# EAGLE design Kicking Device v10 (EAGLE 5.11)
OC_FARNELL: 1685056

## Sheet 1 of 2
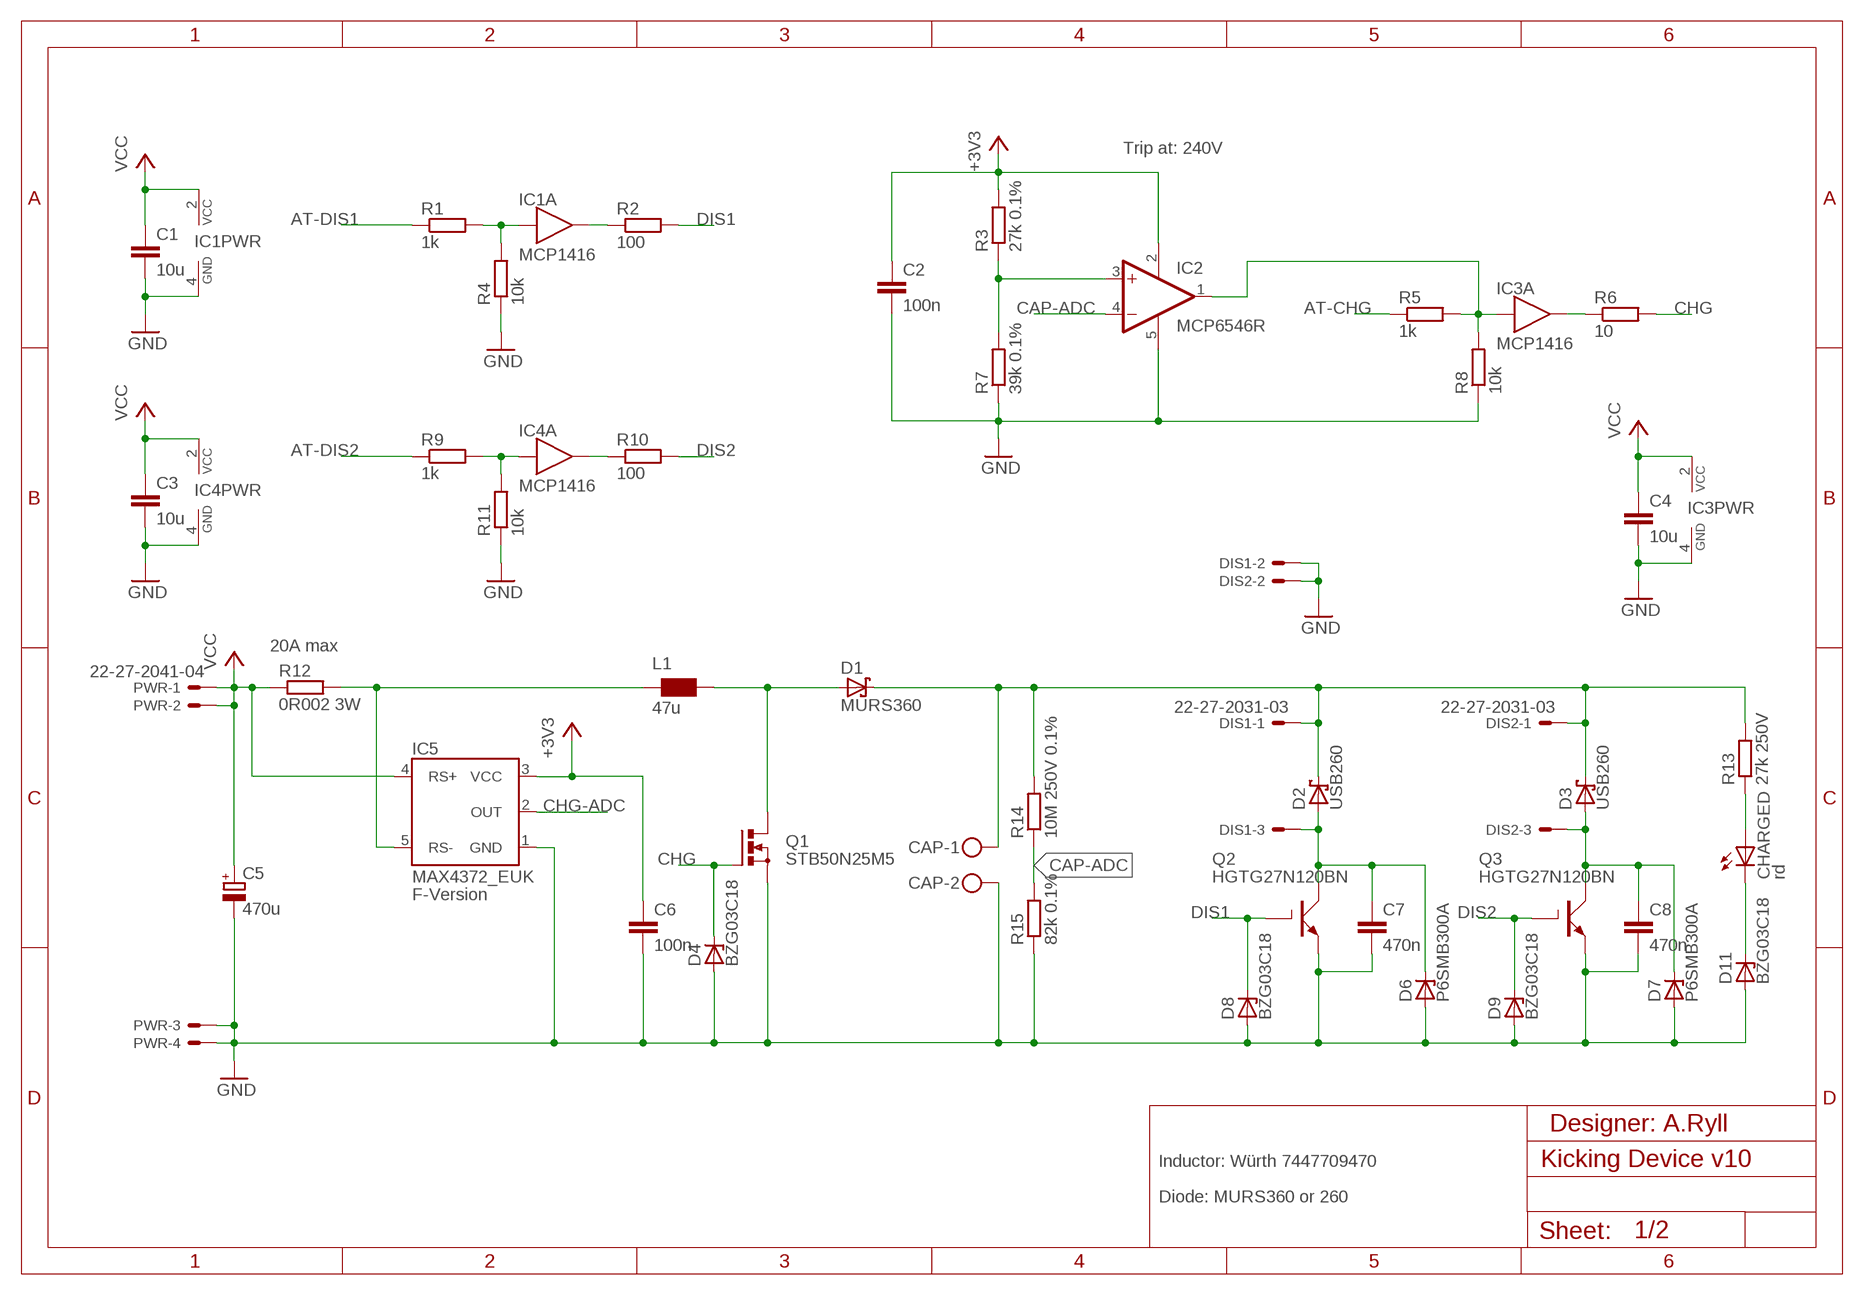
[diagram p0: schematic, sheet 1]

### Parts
C1  10u  C-EUC0805  [C0805]
C2  100n  C-EUC0805  [C0805]
C3  10u  C-EUC0805  [C0805]
C4  10u  C-EUC0805  [C0805]
C5  470u  CPOL-EUG  [PANASONIC_G]
C6  100n  C-EUC0805  [C0805]
C7  470n  C-EUC1812  [C1812]
C8  470n  C-EUC1812  [C1812]
CAP  MKDSN1,5/2-5,08  [MKDSN1,5/2-5,08]
CHARGED  rd  LEDCHIP-LED0805  [CHIP-LED0805]
D1  MURS360  SCHOTTKY-DIODESMC  [SMC]
D2  USB260  SCHOTTKY-DIODESMD  [SMB]
D3  USB260  SCHOTTKY-DIODESMD  [SMB]
D4  BZG03C18  ZENER-DIODESMB  [SMB]
D6  P6SMB300A  ZENER-DIODESMB  [SMB]
D7  P6SMB300A  ZENER-DIODESMB  [SMB]
D8  BZG03C18  ZENER-DIODESMB  [SMB]
D9  BZG03C18  ZENER-DIODESMB  [SMB]
D11  BZG03C18  ZENER-DIODESMB  [SMB]
DIS1  22-27-2031-03  [6410-03]
DIS2  22-27-2031-03  [6410-03]
IC1  MCP1416  [SOT23-5]
IC2  MCP6546R  MCP601R  [SOT23-5]
IC3  MCP1416  [SOT23-5]
IC4  MCP1416  [SOT23-5]
IC5  MAX4372_EUK  [SOT23-5]
L1  47u  WE-PD_L/XL/XXL  [WE-PD_L/XL/XXL]
PWR  22-27-2041-04  [6410-04]
Q1  STB50N25M5  NMOS-D2PAK  [D2PAK]
Q2  HGTG27N120BN  IGBT-TO247  [TO247BV]
Q3  HGTG27N120BN  IGBT-TO247  [TO247BV]
R1  1k  R-EU_R0805  [R0805]
R2  100  R-EU_R0805  [R0805]
R3  27k 0.1%  R-EU_R0805  [R0805]
R4  10k  R-EU_R0805  [R0805]
R5  1k  R-EU_R0805  [R0805]
R6  10  R-EU_R0805  [R0805]
R7  39k 0.1%  R-EU_R0805  [R0805]
R8  10k  R-EU_R0805  [R0805]
R9  1k  R-EU_R0805  [R0805]
R10  100  R-EU_R0805  [R0805]
R11  10k  R-EU_R0805  [R0805]
R12  0R002 3W  R-EU_R2512  [R2512]
R13  27k 250V  R-EU_R1206  [R1206]
R14  10M 250V 0.1%  R-EU_R1206  [R1206]
R15  82k 0.1%  R-EU_R1206  [R1206]

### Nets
400-HIGH [HV]: D1.A L1.1 Q1.2(D)
400-SW: IC5.5(RS-) L1.2 R12.2
+3V3: C2.1 C6.1 IC2.2(V+) IC5.3(VCC) R3.2 ; also sheet 2
AT-CHG: R5.1 ; also sheet 2
AT-DIS1: R1.1 ; also sheet 2
AT-DIS2: R9.1 ; also sheet 2
CAP-ADC: IC2.4(-IN) R14.1 R15.2 ; also sheet 2
CAPVCC [HV]: CAP.1 D1.C D2.C D3.C DIS1.1 DIS2.1 R13.2 R14.2
CHG: D4.C Q1.1(G) R6.2
CHG-ADC: IC5.2(OUT) ; also sheet 2
CHG-IN: IC2.1(OUT) IC3.3(A:IN) R5.2 R8.2
DIS1: D8.C Q2.1(G) R2.2
DIS1-SW [HV]: C7.1 D2.A D6.C DIS1.3 Q2.2(C)
DIS2: D9.C Q3.1(G) R10.2
DIS2-SW [HV]: C8.1 D3.A D7.C DIS2.3 Q3.2(C)
GND: C1.2 C2.2 C3.2 C4.2 C5.- C6.2 C7.2 C8.2 CAP.2 D4.A D6.A D7.A D8.A D9.A D11.A DIS1.2 DIS2.2 IC1.4(PWR:GND) IC2.5(V-) IC3.4(PWR:GND) IC4.4(PWR:GND) IC5.1(GND) PWR.3 PWR.4 Q1.3(S) Q2.3(E) Q3.3(E) R4.1 R7.1 R8.1 R11.1 R15.1 ; also sheet 2
N$2: IC1.3(A:IN) R1.2 R4.2
N$3: IC2.3(+IN) R3.1 R7.2
N$5: IC1.5(A:OUT) R2.1
N$6: CHARGED.A R13.1
N$10: CHARGED.C D11.C
N$11: IC4.3(A:IN) R9.2 R11.2
N$17: IC4.5(A:OUT) R10.1
N$19: IC3.5(A:OUT) R6.1
VCC: C1.1 C3.1 C4.1 C5.+ IC1.2(PWR:VCC) IC3.2(PWR:VCC) IC4.2(PWR:VCC) IC5.4(RS+) PWR.1 PWR.2 R12.1

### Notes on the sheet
- Trip at: 240V
- 20A max
- F-Version
- Designer: A.Ryll
- Inductor: Würth 7447709470
- Diode: MURS360 or 260

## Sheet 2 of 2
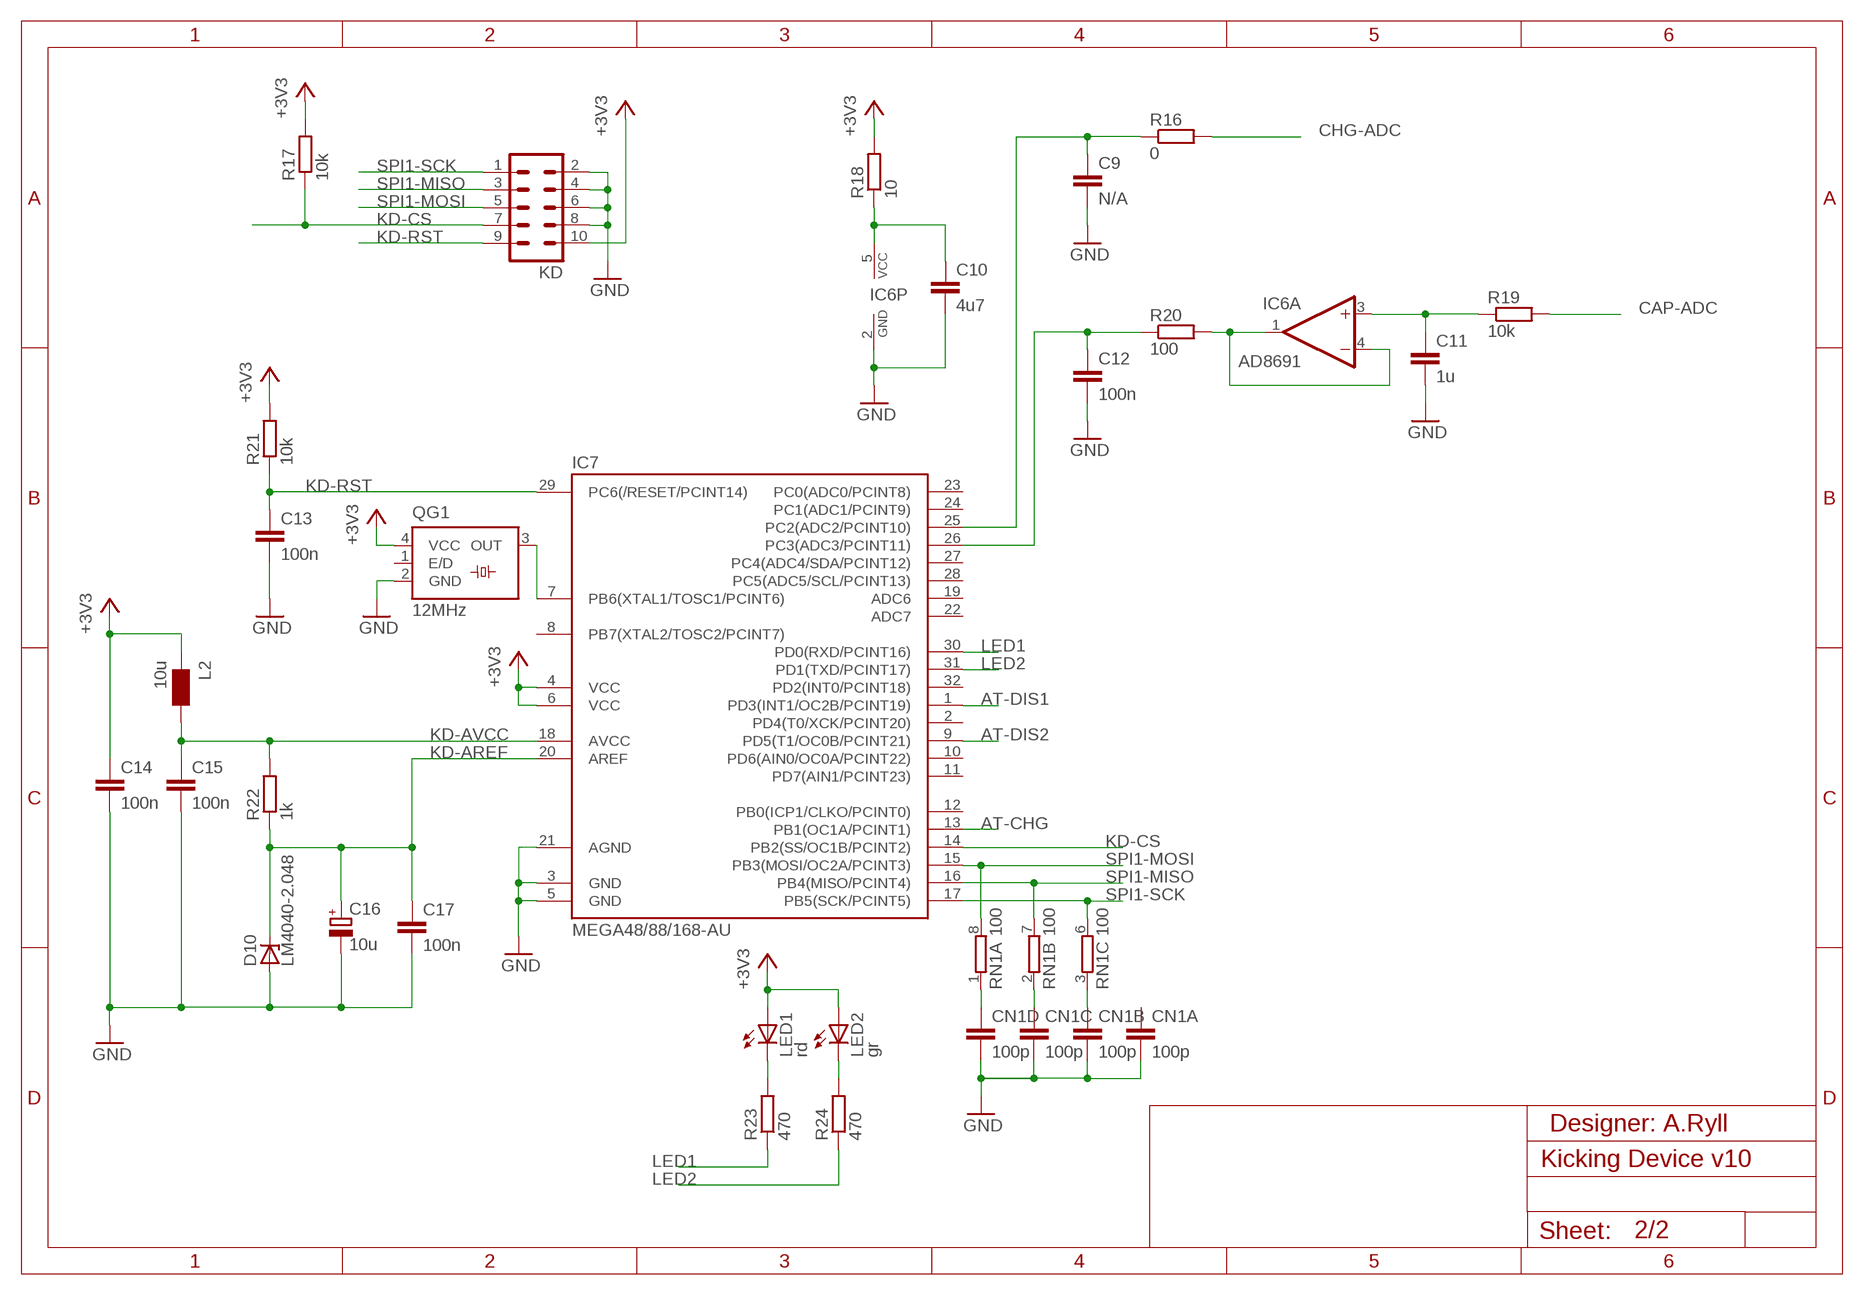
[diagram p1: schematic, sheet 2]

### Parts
C9  N/A  C-EUC0805  [C0805]
C10  4u7  C-EUC0805  [C0805]
C11  1u  C-EUC0805  [C0805]
C12  100n  C-EUC0805  [C0805]
C13  100n  C-EUC0805  [C0805]
C14  100n  C-EUC0805  [C0805]
C15  100n  C-EUC0805  [C0805]
C16  10u  CPOL-EUC/6032-28W  [C/6032-28W]
C17  100n  C-EUC0805  [C0805]
CN1  100p  4C-NCAY16  [CAY16]
D10  LM4040-2.048  ZENER-DIODELM4040  [SOT23]
IC6  AD8691  AD-OP1RT  [SOT23-5]
IC7  MEGA48/88/168-AU  [TQFP32-08]
KD  ML10  [ML10]
L2  10u  WE-MI_0805  [0805]
LED1  rd  LEDCHIP-LED0805  [CHIP-LED0805]
LED2  gr  LEDCHIP-LED0805  [CHIP-LED0805]
QG1  12MHz  SM77H  [SM77H]
R16  0  R-EU_R0805  [R0805]
R17  10k  R-EU_R0805  [R0805]
R18  10  R-EU_R0805  [R0805]
R19  10k  R-EU_R0805  [R0805]
R20  100  R-EU_R0805  [R0805]
R21  10k  R-EU_R0805  [R0805]
R22  1k  R-EU_R0805  [R0805]
R23  470  R-EU_R0805  [R0805]
R24  470  R-EU_R0805  [R0805]
RN1  100  4R-NCAY16  [CAY16]

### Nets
+3V3: C14.1 IC7.4(VCC) IC7.6(VCC) KD.10 L2.1 LED1.A LED2.A QG1.4(VCC) R17.2 R18.2 R21.2 ; also sheet 1
AT-CHG: IC7.13(PB1(OC1A/PCINT1)) ; also sheet 1
AT-DIS1: IC7.1(PD3(INT1/OC2B/PCINT19)) ; also sheet 1
AT-DIS2: IC7.9(PD5(T1/OC0B/PCINT21)) ; also sheet 1
CAP-ADC: R19.2 ; also sheet 1
CHG-ADC: R16.2 ; also sheet 1
GND: C9.2 C10.2 C11.2 C12.2 C13.2 C14.2 C15.2 C16.- C17.2 CN1.5 CN1.6 CN1.7 CN1.8 D10.2(A) IC6.2(P:GND) IC7.3(GND) IC7.5(GND) IC7.21(AGND) KD.2 KD.4 KD.6 KD.8 QG1.2(GND) ; also sheet 1
KD-AREF: C16.+ C17.1 D10.1(C) IC7.20(AREF) R22.1
KD-AVCC: C15.1 IC7.18(AVCC) L2.2 R22.2
KD-CS: IC7.14(PB2(SS/OC1B/PCINT2)) KD.7 R17.1
KD-RST: C13.1 IC7.29(PC6(/RESET/PCINT14)) KD.9 R21.1
LED1: IC7.30(PD0(RXD/PCINT16)) R23.1
LED2: IC7.31(PD1(TXD/PCINT17)) R24.1
N$4: LED1.C R23.2
N$8: LED2.C R24.2
N$15: C10.1 IC6.5(P:VCC) R18.1
N$18: CN1.4 RN1.1
N$31: CN1.3 RN1.2
N$36: C9.1 IC7.25(PC2(ADC2/PCINT10)) R16.1
N$38: CN1.2 RN1.3
N$39: C11.1 IC6.3(A:+IN) R19.1
N$41: C12.1 IC7.26(PC3(ADC3/PCINT11)) R20.1
N$42: IC6.1(A:OUT) IC6.4(A:-IN) R20.2
SPI1-MISO: IC7.16(PB4(MISO/PCINT4)) KD.3 RN1.7
SPI1-MOSI: IC7.15(PB3(MOSI/OC2A/PCINT3)) KD.5 RN1.8
SPI1-SCK: IC7.17(PB5(SCK/PCINT5)) KD.1 RN1.6
XTAL: IC7.7(PB6(XTAL1/TOSC1/PCINT6)) QG1.3(OUT)
Unconnected: CN1.1 IC7.2(PD4(T0/XCK/PCINT20)) IC7.8(PB7(XTAL2/TOSC2/PCINT7)) IC7.10(PD6(AIN0/OC0A/PCINT22)) IC7.11(PD7(AIN1/PCINT23)) IC7.12(PB0(ICP1/CLKO/PCINT0)) IC7.19(ADC6) IC7.22(ADC7) IC7.23(PC0(ADC0/PCINT8)) IC7.24(PC1(ADC1/PCINT9)) IC7.27(PC4(ADC4/SDA/PCINT12)) IC7.28(PC5(ADC5/SCL/PCINT13)) IC7.32(PD2(INT0/PCINT18)) QG1.1(E/D) RN1.4 RN1.5

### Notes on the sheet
- Designer: A.Ryll

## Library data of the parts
C1-C4 C6-C15 C17 = rcl:C-EU: CAPACITOR, European symbol
C5 C16 = rcl:CPOL-EU: POLARIZED CAPACITOR, European symbol
CAP = con-phoenix-508:MKDSN1,5/2-5,08: MKDSN 1,5/ 2-5,08 Printklemme; MPN: MKDSN 1,5/2-5.08; OC_FARNELL: 1792903; OC_NEWARK: 30M2397
CHARGED LED1 LED2 = led:LED: LED
CN1 = Marvin:4C-N: Array Chip Capacitor; OC_FARNELL: unknown; OC_NEWARK: unknown
D1-D3 = diode:SCHOTTKY-DIODE: Schottky Diode
D4 D6-D9 D11 = diode:ZENER-DIODE: Z-Diode
D10 = Marvin:ZENER-DIODE: Z-Diode
DIS1 DIS2 = con-molex:22-?-03: CONNECTOR wire to board 2.54 mm (.1 inch) pitch header
IC1 IC3 IC4 = Marvin:MCP1416
IC2 = linear:MCP601: Single Op Amp 2.7V to 6.0V Single Supply CMOS Source: http://ww1.microchip.com/downloads/en/DeviceDoc/21314g.pdf
IC5 = Marvin:MAX4372
IC6 = Marvin:AD-OP1
IC7 = avr-6:MEGA48/88/168
KD = con-harting-ml:ML10: HARTING
L1 = wuerth-elektronik:WE-PD: SMD-Shielded Power Inductors WE-PD
L2 = wuerth-elektronik:WE-MI: SMD Multilayer Inductor WE-MI
PWR = con-molex:22-?-04: CONNECTOR wire to board 2.54 mm (.1 inch) pitch header
Q1 = Marvin:NMOS-D2PAK
Q2 Q3 = Marvin:IGBT-TO247
QG1 = Marvin:SM77H: 3.3V CMOS Clock Oscillator Source: www.pletronics.com .. sm77h%203.3v.pdf
R1-R24 = rcl:R-EU_: RESISTOR, European symbol
RN1 = resistor-dil:4R-N: Array Chip Resistor Source: RS Component / Phycomp; OC_FARNELL: unknown; OC_NEWARK: unknown

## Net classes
0 default: width 0.152 mm, clearance 0.152 mm
1 HV: width 0.254 mm, drill 0.305 mm, clearance 1.016 mm to class 0, clearance 1.016 mm

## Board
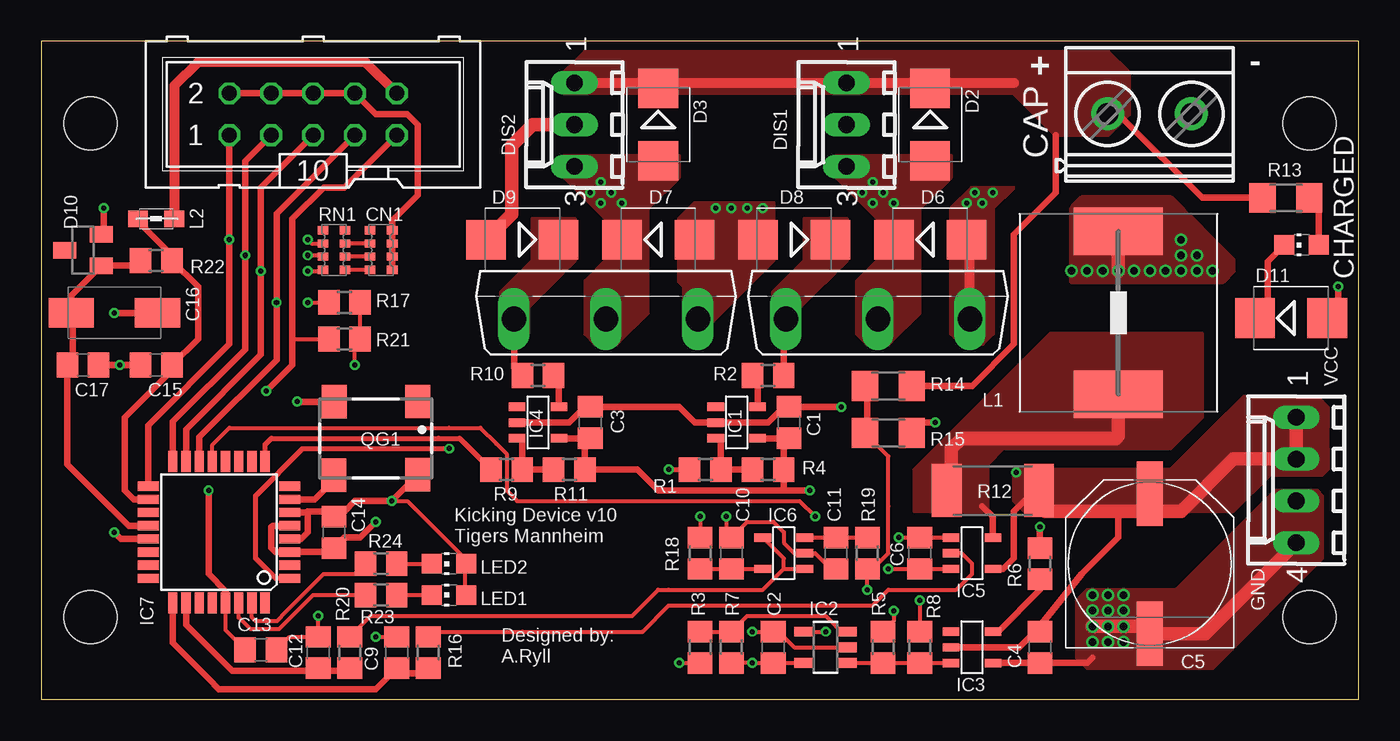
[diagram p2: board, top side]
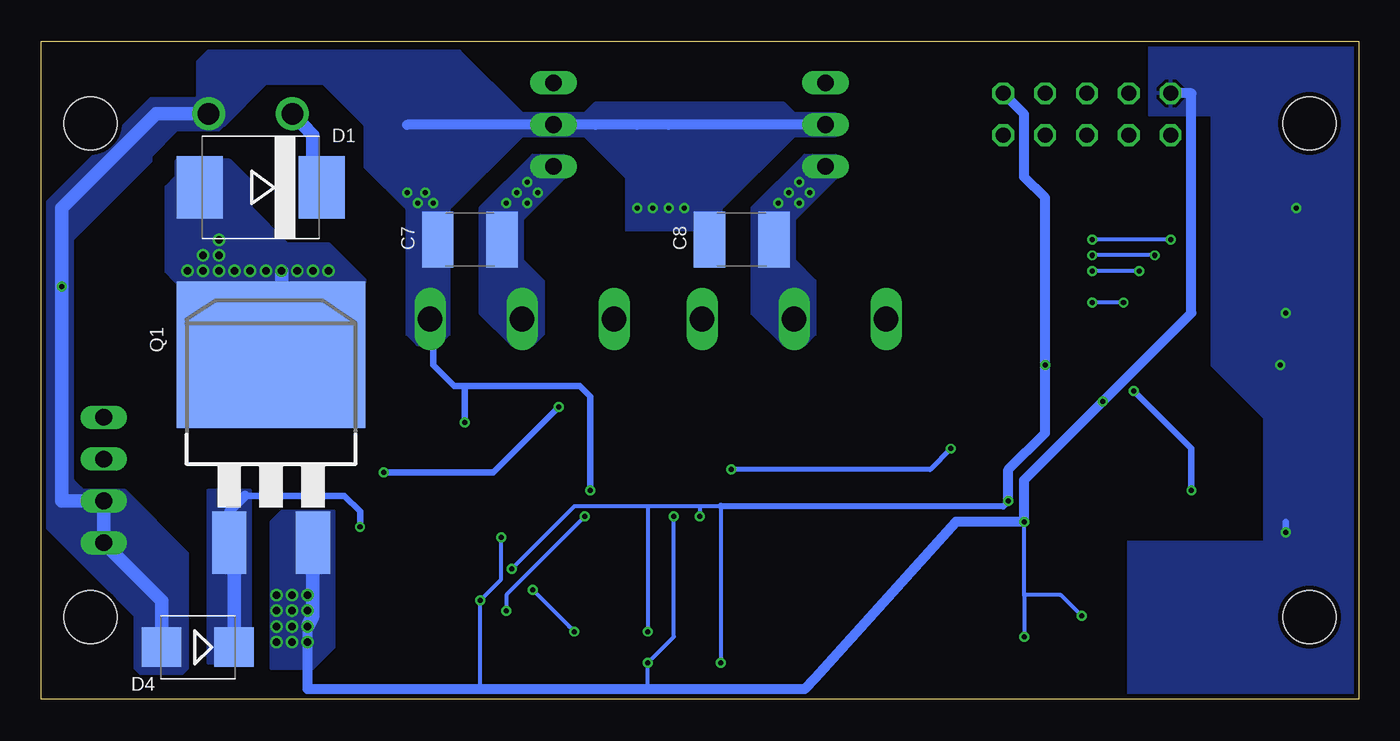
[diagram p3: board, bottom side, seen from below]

Size 80 x 40 mm. Coordinates in mm from the lower left corner, seen from the top.
Outline: 0,0 80,0 80,40 0,40 0,0
Copper layers (1*16): Top 0.035mm / dielectric 1.5mm / Bottom 0.035mm
Design rules "PCB-POOL Standard": minimum track width 0.15mm, minimum drill 0.3mm, track to track 0.15mm, track to pad 0.15mm, pad to pad 0.15mm, via to via 0.15mm, smd to smd 0.15mm, copper to edge 0.3mm, drill to drill 0.2mm, minimum pad ring 0.2mm, minimum via ring 0.15mm, stop-mask expansion 0.075mm, vias tented up to drill 0mil, thermal gap 0.2mm
Holes 3.2 mm at 77,5 77,35 3,35 3,5
tKeepout: area 74,32 to 80,38; area 74,2 to 80,8; area 0,32 to 6,38; area 0,2 to 6,8

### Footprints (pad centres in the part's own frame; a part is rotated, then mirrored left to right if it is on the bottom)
C0805 = smd 1.3 x 1.5: 1 -0.95,0; 2 0.95,0
PANASONIC_G = smd 3.9 x 1.6: + 4.25,0; - -4.25,0
C1812 = smd 1.9 x 3.4: 1 -1.95,0; 2 1.95,0
C/6032-28W = smd 2.75 x 1.8: + 2.625,0; - -2.625,0
MKDSN1,5/2-5,08 = drill 1.3 pad 2 round: 1 -2.561,0.025; 2 2.519,0.025
CHIP-LED0805 = smd 1.2 x 1.2: A 0,-1.05; C 0,1.05
CAY16 = smd 0.5 x 0.65: 1 -1.2,-0.675; 2 -0.4,-0.675; 3 0.4,-0.675; 4 1.2,-0.675; 5 1.2,0.675; 6 0.4,0.675; 7 -0.4,0.675; 8 -1.2,0.675
SMC = smd 2.8 x 3.8: A 3.7,0; C -3.7,0
SMB = smd 2.4 x 2.4: A 2.2,0; C -2.2,0
SOT23 = smd 1 x 1.4: 1 -0.95,-1.1; 2 0.95,-1.1; 3 0,1.1
6410-03 = drill 1.016 long: 1 2.54,0; 2 0,0; 3 -2.54,0
SOT23-5 = smd 1.016 x 0.508: 1 -1.27,0.953; 2 -1.27,0; 3 -1.27,-0.953; 4 1.27,-0.953; 5 1.27,0.953
SOT23-5' = smd 0.6 x 1.2: 1 -0.95,-1.306; 2 0,-1.306; 3 0.95,-1.306; 4 0.95,1.306; 5 -0.95,1.306
TQFP32-08 = smd 1.27 x 0.559: 1 -4.293,2.8; 2 -4.293,2; 3 -4.293,1.2; 4 -4.293,0.4; 5 -4.293,-0.4; 6 -4.293,-1.2; 7 -4.293,-2; 8 -4.293,-2.8; 17 4.293,-2.8; 18 4.293,-2; 19 4.293,-1.2; 20 4.293,-0.4; 21 4.293,0.4; 22 4.293,1.2; 23 4.293,2; 24 4.293,2.8 | smd 0.559 x 1.27: 9 -2.8,-4.293; 10 -2,-4.293; 11 -1.2,-4.293; 12 -0.4,-4.293; 13 0.4,-4.293; 14 1.2,-4.293; 15 2,-4.293; 16 2.8,-4.293; 25 2.8,4.293; 26 2,4.293; 27 1.2,4.293; 28 0.4,4.293; 29 -0.4,4.293; 30 -1.2,4.293; 31 -2,4.293; 32 -2.8,4.293
ML10 = drill 0.914 octagon: 1 -5.08,-1.27; 2 -5.08,1.27; 3 -2.54,-1.27; 4 -2.54,1.27; 5 0,-1.27; 6 0,1.27; 7 2.54,-1.27; 8 2.54,1.27; 9 5.08,-1.27; 10 5.08,1.27
WE-PD_L/XL/XXL = smd 2.9 x 5.4: 1 -4.95,0; 2 4.95,0
0805 = smd 1.2 x 1: 1 -1.1,0; 2 1.1,0
6410-04 = drill 1.016 long: 1 3.81,0; 2 1.27,0; 3 -1.27,0; 4 -3.81,0
D2PAK = smd 2.083 x 3.81: 1 -2.54,-8.89; 3 2.54,-8.89 | smd 11.43 x 8.89: 2 0,2.54
TO247BV = drill 1.499 long: 1 -5.588,-2.921; 2 0,-2.921; 3 5.588,-2.921
SM77H = smd 1.524 x 2.032: 1 -2.545,-2.232; 2 2.535,-2.212; 3 2.545,2.232; 4 -2.535,2.212
R0805 = smd 1.3 x 1.5: 1 -0.95,0; 2 0.95,0
R2512 = smd 1.8 x 3.2: 1 -2.8,0; 2 2.8,0
R1206 = smd 1.6 x 1.803: 1 -1.422,0; 2 1.422,0

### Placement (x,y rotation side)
C1  45.4,16.83 270 top
C2  44.45,3.17 270 top
C3  33.34,16.83 270 top
C4  60.64,3.17 270 top
C5  67.31,8.26 90 top
C6  53.34,8.89 90 top
C7  53.98,27.94 180 bottom
C8  37.47,27.94 180 bottom
C9  21.59,2.86 90 top
C10  41.91,8.89 90 top
C11  48.26,8.89 270 top
C12  16.83,2.86 90 top
C13  13.34,3.02 0 top
C14  17.78,10.16 270 top
C15  6.99,20.32 180 top
C16  4.45,23.5 180 top
C17  2.54,20.32 0 top
CAP  67.31,35.56 0 top
CHARGED  76.52,27.62 90 top
CN1  20.64,27.3 270 top
D1  66.67,31.11 180 bottom
D2  53.98,34.92 270 top
D3  37.47,34.92 270 top
D4  70.48,3.17 180 bottom
D6  53.98,27.94 0 top
D7  37.47,27.94 0 top
D8  45.72,27.94 180 top
D9  29.21,27.94 180 top
D10  2.54,27.3 90 top
D11  75.88,23.18 0 top
DIS1  48.9,34.92 90 top
DIS2  32.38,34.92 90 top
IC1  42.23,16.83 0 top
IC2  MCP6546R  [SOT23-5']  47.62,3.17 90 top
IC3  56.52,3.17 0 top
IC4  30.16,16.83 0 top
IC5  56.52,8.89 0 top
IC6  45.09,8.89 180 top
IC7  10.79,10.16 180 top
KD  16.51,35.56 0 top
L1  65.41,23.5 270 top
L2  6.99,29.21 180 top
LED1  24.77,6.35 90 top
LED2  24.77,8.26 90 top
PWR  76.2,13.34 90 top
Q1  66.04,18.41 0 bottom
Q2  50.8,26.04 0 top
Q3  34.29,26.04 0 top
QG1  20.32,15.88 180 top
R1  40.32,13.97 0 top
R2  44.13,19.68 0 top
R3  40.01,3.17 270 top
R4  44.13,13.97 180 top
R5  51.12,3.17 270 top
R6  60.64,8.26 90 top
R7  41.91,3.17 90 top
R8  53.34,3.17 270 top
R9  28.26,13.97 0 top
R10  30.16,19.68 180 top
R11  32.07,13.97 180 top
R12  57.78,12.7 180 top
R13  75.56,30.48 180 top
R14  51.44,19.05 0 top
R15  51.44,16.19 180 top
R16  23.5,2.86 90 top
R17  18.41,24.13 0 top
R18  40.01,8.89 90 top
R19  50.16,8.89 270 top
R20  18.73,2.86 90 top
R21  18.41,21.91 0 top
R22  6.99,26.67 0 top
R23  20.64,6.35 0 top
R24  20.64,8.26 0 top
RN1  17.78,27.3 90 top

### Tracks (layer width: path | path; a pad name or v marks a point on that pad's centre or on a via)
400-HIGH  (via drill 0.46)
  Top 0.813: v65.41,26.04 L1.1
  Bottom 0.813: v65.41,26.04 65.41,21.59 Q1.2 66.67,20.32
  other vias: 64.45,26.04 63.5,26.04 62.55,26.04 66.36,26.04 67.31,26.04 68.26,26.04 69.22,26.04 70.17,26.04 71.12,26.04 69.22,26.99 69.22,27.94 70.17,26.99
  pour Bottom (no thermals): 60.33,25.4 62.55,27.62 65.09,27.62 67.31,29.84 67.31,31.43 68.58,32.7 71.75,32.7 71.75,31.75 72.39,31.11 72.39,26.04 71.75,25.4
  pour Top (no thermals): 63.18,30.48 62.55,29.84 62.55,25.4 71.75,25.4 72.39,26.04 72.39,26.67 68.58,30.48
400-SW
  Top 0.406: IC5.5 57.78,11.11 57.15,11.75
  Top 0.813: 54.98,13.71 55.24,13.65 55.24,15.24 55.88,15.88 65.28,15.88 65.41,16 L1.2
  pour Top (no thermals): 53.02,11.43 57.47,11.43 57.47,14.29 58.42,15.24 68.58,15.24 70.48,17.14 70.48,22.23 61.28,22.23 53.02,13.97
+3V3  (via drill 0.3)
  Top 0.254: IC2.2 45.72,3.17 45.09,3.81 44.77,4.12 C2.1 v43.18,4.13 | v40.01,11.11 R18.2 | v51.44,7.94 C6.1 IC5.3 | R3.2 v38.73,2.22 | v21.27,12.06 22.23,12.06 25.82,8.47 LED2.A 25.72,8.16 25.72,7.3 25.72,6.45 LED1.A | R17.2 R21.2 19.05,21.59 v19.05,20.32
  Top 0.406: IC7.4 15.79,9.76 16.19,10.16 16.19,11.43 | IC7.6 16.12,11.36 16.19,11.43 | 16.19,11.43 16.51,11.43 17.78,11.43 C14.1 17.78,11.43 18.42,11.43 19.05,12.06 v21.27,12.06 22.86,13.65 QG1.4
  Top 0.61: L2.1 8.09,37.3 9.53,38.73 19.68,38.73 KD.10
  Bottom 0.254: 43.18,11.75 v43.18,4.13 | 40.01,11.75 43.18,11.75 | 40.01,11.75 38.73,11.75 v38.73,2.22 | v51.44,7.94 47.62,11.75 43.18,11.75 | 40.01,11.75 v40.01,11.11 | 19.05,19.05 v19.05,20.32
  Bottom 0.406: v21.27,12.06 21.59,11.75 38.73,11.75
  Bottom 0.61: KD.10 20.32,35.56 20.32,31.75 19.05,30.48 v19.05,20.32 19.05,19.05 19.05,16.19 21.27,13.97 v21.27,12.06
AT-CHG  (via drill 0.3)
  Top 0.254: IC7.13 10.39,15.47 11.43,16.51 24.77,16.51 26.67,16.51 27.62,15.56 28.26,14.92 28.26,12.7 28.89,12.06 30.16,12.06 38.1,12.06 46.04,12.06 v46.99,11.11 | R5.1 51.75,4.76 v51.75,5.4
  Bottom 0.254: v51.75,5.4 51.75,6.35 v46.99,11.11
AT-DIS1  (via drill 0.3)
  Top 0.305: IC7.1 14.23,7.36 13.02,8.57 13.02,12.38 15.88,15.24 v24.77,15.24 | v38.1,13.97 R1.1
  Bottom 0.305: v24.77,15.24 26.04,13.97 v38.1,13.97
AT-DIS2
  Top 0.305: IC7.9 13.6,15.5 13.97,15.88 24.13,15.88 25.4,15.88 R9.1
CAP-ADC  (via drill 0.3)
  Top 0.254: v50.16,6.67 R19.2 50.48,7.94 51.44,8.89 51.44,11.75 51.44,14.77 R15.2 | v47.62,4.13 v47.62,4.12 IC2.4
  Top 0.406: R14.1 50.16,18.9 50.16,16.83 50.16,16.34 R15.2
  Bottom 0.254: v50.16,6.67 47.94,4.45 v47.62,4.13
CAPVCC
  Top 0.406: R14.2 56.52,19.05 59.05,21.59 59.05,28.26 61.59,30.8 61.59,34.29 | R13.2 70.48,30.48 65.72,35.24 65.38,35.59 CAP.1
  Top 0.61: DIS2.1 37.12,37.47 D3.C 37.8,37.47 DIS1.1 53.63,37.47 D2.C 54.31,37.47 59.05,37.47
  Bottom 0.813: D1.C 62.98,31.86 | 62.98,31.86 63.5,32.38 63.5,34.29 64.72,35.56 CAP.1 | 62.98,31.86 63.5,31.86
  pour Top (no thermals): 31.11,37.47 33.02,39.37 64.77,39.37 66.04,38.1 66.04,35.56 64.77,34.29 61.59,34.29 59.05,36.83 31.75,36.83
CHG  (via drill 0.3)
  Top 0.406: R6.2 v60.64,10.48
  Bottom 0.406: v60.64,10.48 60.64,11.43 61.59,12.38 67.63,12.38
  Bottom 0.61: 67.63,12.38 68.58,11.43 68.58,10.79
  Bottom 0.813: 68.58,10.79 Q1.1 68.28,7.96 D4.C
  pour Bottom (no thermals): 67.31,12.7 67.31,2.22 69.85,2.22 69.85,12.7
CHG-ADC
  Top 0.254: IC5.2 55.88,8.89 56.52,8.26 56.52,7.62 55.88,6.99 55.56,6.67 51.44,6.67 50.8,6.03 50.48,5.71 38.1,5.71 36.51,4.13 29.21,4.13 23.82,4.13 R16.2
CHG-IN
  Top 0.254: IC2.1 R5.2 R8.2 IC3.3
DIS1
  Top 0.406: R2.2 45.08,22.98 Q2.1
  pour Top (no thermals): 44.45,22.23 44.45,24.77 46.35,26.67 46.35,29.21 48.9,29.21 48.9,26.67 46.04,23.81 46.04,22.23
DIS1-SW  (via drill 0.3)
  other vias: 51.75,30.16 50.48,30.16 51.12,30.8 49.85,30.8 50.48,31.43
  pour Top (no thermals): 51.44,21.59 52.7,22.86 53.34,23.5 53.34,29.84 55.24,31.75 55.24,33.02 48.26,33.02 47.62,32.38 50.8,29.21 50.8,26.67 49.53,25.4 49.53,22.23 50.16,21.59
  pour Bottom (no thermals): 49.53,22.23 49.53,25.4 50.8,26.67 50.8,29.21 47.62,32.38 48.26,33.02 50.16,33.02 53.34,29.84 53.34,23.5 51.44,21.59 50.16,21.59
DIS2
  Top 0.406: R10.2 28.73,20.16 28.73,21.75 28.73,23.08 Q3.1
  pour Top (no thermals): 27.94,22.23 27.94,24.77 29.84,26.67 29.84,29.21 32.38,29.21 32.38,26.67 29.53,23.81 29.53,22.23
DIS2-SW  (via drill 0.3)
  other vias: 33.97,30.16 33.34,30.8 34.61,30.8 35.24,30.16 33.97,31.43
  pour Bottom (no thermals): 33.02,22.23 33.02,25.4 34.29,26.67 34.29,29.21 31.11,32.38 31.75,33.02 33.66,33.02 36.83,29.84 36.83,23.5 34.92,21.59 33.66,21.59
  pour Top (no thermals): 34.92,21.59 36.2,22.86 36.83,23.5 36.83,29.84 38.73,31.75 38.73,33.02 31.75,33.02 31.11,32.38 34.29,29.21 34.29,26.67 33.02,25.4 33.02,22.23 33.66,21.59
GND  (via drill 0.3, 0.46)
  Top 0.254: v41.59,11.11 41.59,10.16 C10.2 42.87,10.79 44.45,10.79 45.09,10.16 45.09,9.53 45.72,8.89 IC6.2 46.99,8.89 47.62,8.26 47.94,7.94 C11.2 | v52.07,9.84 C6.2 IC5.1 | IC2.5 C2.2 v43.18,2.23 v43.18,2.22 R7.1 | v53.34,6.03 R8.1 | v16.83,5.08 C12.2 15.08,3.81 C13.2 | C9.2 v20.32,3.81
  Top 0.305: 33.02,15.88 C3.2
  Top 0.406: KD.2 KD.4 KD.6 KD.8 20.32,35.56 21.27,35.56 22.23,35.56 22.86,34.92 22.86,30.64 21.43,29.21 21.31,29.09 21.31,28.57 | IC7.21 4.84,9.76 v4.45,10.16 | C17.2 v4.76,20.32 C15.2 | v4.45,23.5 C16.- | D10.2 3.81,28.25 3.81,28.26 v3.81,29.84 | IC7.5 14.05,10.56 13.97,10.48 13.97,9.21 14.22,8.96 IC7.3 17.53,8.96 C14.2 | C14.2 17.78,8.89 | IC1.4 C1.2 45.08,15.88 R4.1 45.08,12.7 45.09,12.7 | C14.2 18.41,9.84 19.37,9.84 v20.32,10.79 | C3.2 IC4.4 | 45.09,12.7 37.47,12.7 36.2,13.97 R11.1 33.02,15.88 | 45.09,12.7 v46.67,12.7 | IC3.4 C4.2 61.91,2.22 63.5,2.22 63.82,2.54 | QG1.2 15.57,18.09 v15.56,18.1 | R15.1 53.49,16.83 v54.29,16.83 | 21.31,28.57 CN1.8 | CN1.8 CN1.7 CN1.6 CN1.5 | 21.31,28.57 CN1.8 | D11.A 78.74,23.84 v78.74,25.08
  Top 0.61: Q2.3 56.39,27.73 D6.A
  Top 0.813: v63.82,4.45 66.87,4.45 C5.- 70.68,4 PWR.4 | D9.A 28.57,29.5 28.57,32.38 28.57,33.66 29.84,34.92 DIS2.2
  Bottom 0.254: v41.59,11.11 41.59,3.81 v43.18,2.22 43.18,0.64 | v52.07,9.84 52.07,7.3 v53.34,6.03 53.34,0.64 | v20.32,10.79 20.32,8.57 20.32,7.3 20.32,6.35 | 20.32,6.35 v20.32,3.81 | v16.83,5.08 18.1,6.35 20.32,6.35
  Bottom 0.406: v4.45,10.16 4.45,10.79 | v46.67,12.7 46.67,18.41 47.31,19.05 48.26,19.05 54.29,19.05 | Q1.3 63.5,10.47 | v15.56,18.1 15.24,18.41 | 54.29,19.05 54.93,19.05 56.2,20.32 56.2,22.92 Q2.3 | 54.29,19.05 v54.29,16.83 | 78.74,24.45 v78.74,25.08
  Bottom 0.61: KD.2 10.16,36.83 10.16,23.5 12.06,21.59 13.97,19.68 15.24,18.41 v15.56,18.1 17.78,15.88 20.32,13.34 v20.32,10.79 24.45,10.79 33.02,1.27 33.66,0.64 38.1,0.64 43.18,0.64 47.31,0.64 53.34,0.64 56.83,0.64 63.82,0.64 v63.82,4.45 | DIS2.2 41.91,34.92 43.81,34.92 46.35,34.92 DIS1.2 57.78,34.92
  Bottom 0.813: CAP.2 73,35.59 78.74,29.84 v78.74,25.08 78.74,24.45 78.74,12.06 PWR.3 PWR.4 72.69,6.01 D4.A | Q1.3 63.5,5.08 v63.82,4.45
  other vias: 64.77,6.35 65.72,6.35 63.82,6.35 63.82,5.4 64.77,5.4 65.72,5.4 64.77,4.45 65.72,4.45 63.82,3.49 64.77,3.49 65.72,3.49 43.81,29.84 42.86,29.84 41.91,29.84 40.96,29.84 56.2,30.16 57.15,30.16 56.67,30.8 57.78,30.8
  pour Bottom: 0,40.01 12.7,40.01 12.7,35.56 8.89,35.56 8.89,20.32 5.71,17.14 5.71,9.53 13.97,9.53 13.97,0 0,0
  pour Top (no thermals): 77.47,12.7 77.79,12.38 77.79,8.57 71.12,1.91 63.5,1.91 62.87,2.54 62.87,6.03 63.5,6.67 68.9,6.67 74.93,12.7
  pour Bottom (no thermals): 62.23,11.43 65.41,11.43 66.04,10.79 66.04,1.91 63.5,1.91 62.87,2.54 62.23,3.17
  pour Bottom (no thermals): 77.47,12.7 77.79,12.38 77.79,8.57 74.3,5.08 74.3,1.91 73.98,1.59 71.44,1.59 71.12,1.91 71.12,8.89 74.93,12.7
  pour Bottom (no thermals): 77.47,12.7 78.11,13.34 78.11,27.94 73.34,32.7 73.34,33.02 71.75,34.61 69.22,34.61 68.58,35.24 68.58,35.88 69.22,36.51 73.34,36.51 80.01,29.84 80.01,10.79 77.79,8.57 77.79,12.38
  pour Bottom (no thermals): 31.75,35.56 34.29,35.56 34.92,36.2 46.35,36.2 46.99,35.56 48.9,35.56 48.9,34.29 46.99,34.29 44.45,31.75 44.45,28.57 38.73,28.57 38.73,29.84 34.29,34.29 31.75,34.29
  pour Bottom (no thermals): 48.9,35.56 50.8,35.56 54.61,39.37 69.85,39.37 70.48,38.73 70.48,35.56 69.85,34.92 68.9,34.92 66.36,37.47 62.87,37.47 60.33,34.92 60.33,32.38 57.78,29.84 57.78,22.23 57.15,21.59 55.88,21.59 55.24,22.23 55.24,29.84 50.8,34.29 48.9,34.29
  pour Top (no thermals): 55.88,21.59 55.24,22.23 55.24,29.84 56.52,31.11 59.05,31.11 57.78,29.84 57.78,22.23 57.15,21.59
  pour Top (no thermals): 39.05,22.23 39.05,25.08 38.73,25.4 38.73,29.21 39.69,30.16 44.45,30.16 44.45,26.67 40.64,22.86 40.64,22.23
KD-AREF
  Top 0.406: IC7.20 5.32,10.56 1.59,14.29 C17.1 | R22.1 5.72,26.36 D10.1 1.82,24.54 C16.+ 1.91,23.41 1.91,20.64 C17.1 | C17.1 1.27,20
KD-AVCC
  Top 0.406: IC7.18 5.62,12.16 5.08,12.7 5.08,17.14 7.93,20 C15.1 9.53,21.91 9.53,25.08 R22.2 7.93,26.99 5.88,29.04 L2.2
KD-CS  (via drill 0.3)
  Top 0.254: v16.19,24.13 R17.1 | 14.29,23.81 v14.29,24.13
  Top 0.406: IC7.14 9.6,15.95 14.29,20.64 14.29,23.81 v14.29,24.13 14.29,29.53 KD.7
  Bottom 0.254: v14.29,24.13 v16.19,24.13
KD-RST  (via drill 0.3)
  Top 0.254: C13.1 11.2,4.21 IC7.29 | 15.24,21.91 R21.1
  Top 0.406: KD.9 18.41,31.11 17.14,31.11 15.24,29.21 15.24,21.91 15.24,20.32 v13.65,18.73 | v10.16,12.7 10.16,7.62 11.2,6.58 IC7.29
  Bottom 0.406: v13.65,18.73 10.16,15.24 v10.16,12.7
LED1
  Top 0.254: IC7.30 11.99,4.99 12.7,4.29 14.45,4.29 15.24,5.08 16.51,6.35 R23.1
LED2
  Top 0.254: IC7.31 12.79,4.99 13.02,4.76 14.29,4.76 14.92,5.4 17.14,7.62 19.05,7.62 R24.1
N$2
  Top 0.406: 41.28,15.88 IC1.3 41.27,15.88 R1.2 R4.2
N$3
  Top 0.254: R3.1 R7.2 42.86,5.08 47.62,5.08 48.26,4.45 48.58,4.12 IC2.3
N$4
  Top 0.254: R23.2 LED1.C
N$5
  Top 0.406: IC1.5 43.5,19.37 R2.1
N$6
  Top 0.406: CHARGED.A 77.57,29.9 R13.1
N$8
  Top 0.254: R24.2 LED2.C
N$10
  Top 0.406: CHARGED.C 74.47,26.62 74.47,23.96 D11.C
N$11
  Top 0.305: 29.21,15.88 IC4.3
  Top 0.406: IC4.3 29.21,15.88 | R11.2 R9.2 29.21,15.88
N$15
  Top 0.254: R18.1 C10.1 IC6.5
N$17
  Top 0.406: IC4.5 31.43,19.36 R10.1
N$18
  Top 0.254: CN1.4 RN1.1
N$19
  Top 0.406: IC3.5 58.1,4.13 60.64,6.67 R6.1
N$31
  Top 0.254: CN1.3 RN1.2
N$36
  Top 0.406: IC7.25 8,3.44 10.16,1.27 10.79,0.64 19.37,0.64 20.32,0.64 C9.1 21.91,1.59 22.54,1.59 23.18,1.59 R16.1
N$38
  Top 0.254: CN1.2 RN1.3
N$39
  Top 0.254: IC6.3 C11.1 R19.1
N$41
  Top 0.406: IC7.26 8.79,4.54 11.59,1.75 16.67,1.75 C12.1 16.99,1.75 17.78,1.75 18.57,1.75 R20.1
N$42
  Top 0.254: 45.09,7.94 IC6.1 | 45.09,7.94 43.81,6.67 38.1,6.67 37.47,6.67 35.88,5.08 29.21,5.08 20,5.08 R20.2 | IC6.4 45.09,8.57 45.09,7.94
SPI1-MISO  (via drill 0.3)
  Top 0.254: RN1.7 17.02,26.99 v16.19,26.99
  Top 0.406: IC7.16 8,16.89 12.38,21.27 v12.38,26.99 12.38,32.7 KD.3
  Bottom 0.254: v12.38,26.99 v16.19,26.99
SPI1-MOSI  (via drill 0.3)
  Top 0.254: RN1.8 17.04,26.04 v16.19,26.04 | 13.34,25.4 v13.34,26.04
  Top 0.406: IC7.15 8.79,16.41 13.34,20.95 13.34,25.4 v13.34,26.04 13.34,26.67 13.34,31.11 KD.5
  Bottom 0.254: v13.34,26.04 v16.19,26.04
SPI1-SCK  (via drill 0.3)
  Top 0.254: RN1.6 16.43,27.7 v16.19,27.94
  Top 0.406: IC7.17 6.5,16.66 11.43,21.59 v11.43,27.94 KD.1
  Bottom 0.254: v11.43,27.94 v16.19,27.94
VCC  (via drill 0.3)
  Top 0.406: C1.1 45.09,17.78 44.13,16.83 IC1.2 39.69,16.83 38.74,17.78 C3.1 33.02,17.78 32.07,16.83 IC4.2 | C1.1 | IC3.2 59.37,3.17 60.01,3.81 60.32,4.12 C4.1 60.64,4.45 63.18,7.62 65.41,9.84 65.41,10.16 65.41,11.43 | IC5.4 58.42,7.94 59.05,8.57 59.05,11.43 59.69,12.06 | v48.58,17.78 C1.1
  Top 0.813: PWR.1 PWR.2 72.39,14.61 69.22,11.43 67.5,11.43 C5.+ 67.11,11.43 65.41,11.43 62.87,11.43 60.96,11.43 60.59,11.8
  Bottom 0.406: v59.21,13.81 52.55,13.81 v48.58,17.78
  pour Top (no thermals): 59.05,12.06 59.05,13.97 68.58,13.97 73.03,18.41 77.47,18.41 78.11,17.78 78.11,13.97 77.79,13.65 74.61,13.65 72.39,11.43 59.69,11.43
XTAL
  Top 0.406: IC7.7 16.61,12.16 17.14,12.7 17.77,13.33 QG1.3

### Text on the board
tPlace: + | - | VCC | Kicking Device v10 | Tigers Mannheim | GND | Designed by: | A.Ryll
